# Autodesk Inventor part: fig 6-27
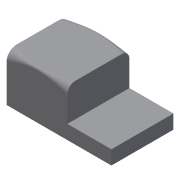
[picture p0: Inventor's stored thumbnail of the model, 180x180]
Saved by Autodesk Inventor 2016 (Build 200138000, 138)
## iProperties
Created: 2004-05
Part Number: fig 6-27
Document SubType Name: Modeling
Designer: CADCIM Technologies
Manufacturer: Standard
Standards Organization: Custom
Density: 1 g/cm^3
Material: Generic
Appearance: Default
Author: CADCIM Technologies
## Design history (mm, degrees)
node "Sketch1"
sketch "Sketch2"
  geometry: L1 (0.098, 47.711)-(0.098, 0.049); L2 (0.098, 0.049)-(-105.483, 0.049); L3 (-105.483, 0.049)-(-105.483, 14.192); L4 (-105.483, 14.192)-(-61.139, 14.192); L5 (-61.139, 14.192)-(-61.139, 47.711); L6 (-61.139, 47.711)-(0.098, 47.711)
  constraints: 12 end point, 3 parallel, 2 perpendicular, 1 vertical
extrude "Extrusion1" new body sketch "Sketch2" stored distance "d0" = 62.5; taper "d1" = 0 deg
fillet "Fillet9" dims "d61" = 10, "d62" = 8, "d63" = 2, "d64" = 5
fillet "Fillet10" dims "d65" = 8, "d66" = 10, "d67" = 2, "d68" = 5
body "Solid1"
